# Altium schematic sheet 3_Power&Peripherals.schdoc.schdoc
size 309 x 223 mm; Symbol: Artery_A4; Device: Artery_A4; Company: Artery Technology; Version: 1.1; Page Size: A4; @Project Name: AT-START-F423 V1.1; @Page Count: 4; @Update Date: 2023-04-24; @Create Date: 2023-04-24; @Schematic Name: AT-START-F423 V1.1; @Page No: 3; @Page Name: Power&Peripherals
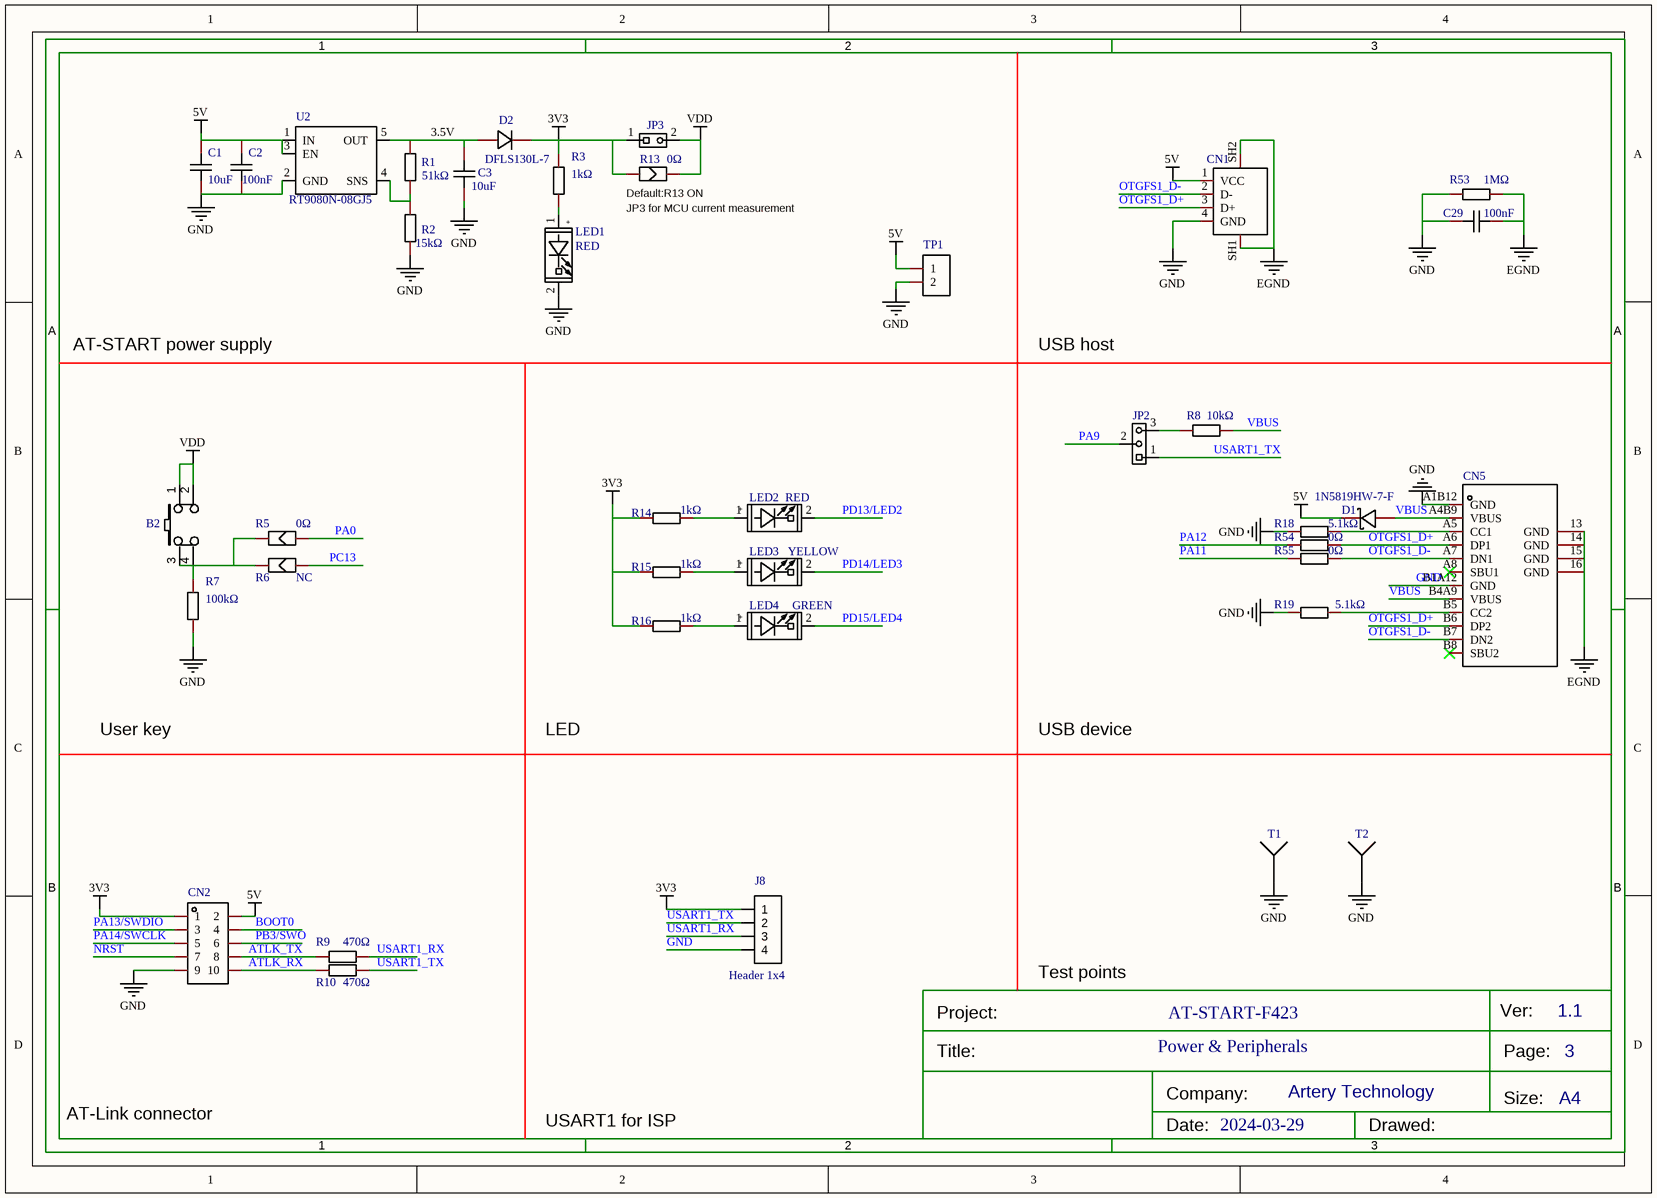
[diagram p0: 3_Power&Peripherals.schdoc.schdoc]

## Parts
B2  BUTTON_SMT,6.0x6.0x4.5mm  [BUTTON_SMT_6*6*5]  (value not drawn)
C1  value 10uF  [C0603]  (hidden comment: CL10A106KP8NNNC)
C2  value 100nF  [C0603]  (hidden comment: CC0603KRX7R9BB104)
C3  value 10uF  [C0603]  (hidden comment: CL10A106KP8NNNC)
C29  value 100nF  [C0603]  (hidden comment: CC0603KRX7R9BB104)
CN1  902-131A1011D10100  [USB-A-TH__USB-AF-90]  (value not drawn)
CN2  Z-21310110021001  [HDR-TH_10P-P2.54-V-M-R2-C5-S2.54]  (value not drawn)
CN5  TYPEC-304-BCP16  [USB-C-SMD_TYPEC-304-BCP16]  (value not drawn)
D1  1N5819HW-7-F  [SOD-123_L2.8-W1.8-LS3.7-FD]
D2  DFLS130L-7  [POWERDI-123_L2.8-W1.8-LS3.7-RD]
J8  Header 1x4  [HDR1X4]
JP2  Header 1x3  [HEADER 1X3]  (value not drawn)
JP3  NC(Header 1x2)  [HDR1X2]  (value not drawn)
LED1  RED  [LED0603]
LED2  RED  [LED0603]
LED3  YELLOW  [LED0603]
LED4  GREEN  [LED0603]
R1  value 51kΩ  [R0603]  (hidden comment: 0603WAF5102T5E)
R2  value 15kΩ  [R0603]  (hidden comment: 0603WAF1502T5E)
R3  value 1kΩ  [R0603]  (hidden comment: 0603WAF1001T5E)
R5  0Ω  [SB-PAD]
R6  NC  [SB-PAD]
R7  value 100kΩ  [R0603]  (hidden comment: 0603WAF1003T5E)
R8  value 10kΩ  [R0603]  (hidden comment: 0603WAF1002T5E)
R9  value 470Ω  [R0603]  (hidden comment: 0603WAF4700T5E)
R10  value 470Ω  [R0603]  (hidden comment: 0603WAF4700T5E)
R13  0Ω  [SB-PAD]
R14  value 1kΩ  [R0603]  (hidden comment: 0603WAF1001T5E)
R15  value 1kΩ  [R0603]  (hidden comment: 0603WAF1001T5E)
R16  value 1kΩ  [R0603]  (hidden comment: 0603WAF1001T5E)
R18  value 5.1kΩ  [R0603]  (hidden comment: 0603WAF5101T5E)
R19  value 5.1kΩ  [R0603]  (hidden comment: 0603WAF5101T5E)
R53  value 1MΩ  [R0603]  (hidden comment: RC0603FR-071ML)
R54  value 0Ω  [R0603]  (hidden comment: 0603WAF220JT5E)
R55  value 0Ω  [R0603]  (hidden comment: 0603WAF220JT5E)
T1  Testpoint  [TESTHOOK]  (value not drawn)
T2  Testpoint  [TESTHOOK]  (value not drawn)
TP1  2.54-1*2P母  [AT-START-TEST-POINT 1X2]  (value not drawn)
U2  RT9080N-08GJ5  [SOT-23-5(1)]

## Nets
3V3: CN2.1 D2.1 J8.1 JP3.1 R3.2 R13.1 R14.2 R15.2 R16.2
5V: C1.2 C2.2 CN1.1(VCC) CN2.2 D1.2(K) TP1.1 U2.1(IN) U2.3(EN)
EGND: C29.2 CN1.SH1 CN1.SH2 CN5.13(GND) CN5.14(GND) CN5.15(GND) CN5.16(GND) R53.1
GND: C1.1 C2.1 C3.1 C29.1 CN1.4(GND) CN2.9 CN5.A1B12(GND) CN5.B1A12(GND) J8.4 LED1.2(CATHODE) R2.1 R7.1 R18.2 R19.2 R53.2 T1.1 T2.1 TP1.2 U2.2(GND)
VDD: B2.1 B2.2 JP3.2 R13.2
ATLK_RX: CN2.10 R10.1
ATLK_TX: CN2.8 R9.1
BOOT0: CN2.4
NRST: CN2.7
OTGFS1_D+: CN1.3(D+) CN5.A6(DP1) CN5.B6(DP2) R54.2
OTGFS1_D-: CN1.2(D-) CN5.A7(DN1) CN5.B7(DN2) R55.2
PA0: R5.1
PA9: JP2.2
PA11: R55.1
PA12: R54.1
PA13/SWDIO: CN2.3
PA14/SWCLK: CN2.5
PB3/SWO: CN2.6
PC13: R6.1
PD13/LED2: LED2.2(CATHODE)
PD14/LED3: LED3.2(CATHODE)
PD15/LED4: LED4.2(CATHODE)
USART1_RX: J8.3 R9.2
USART1_TX: J8.2 JP2.1 R10.2
VBUS: CN5.A4B9(VBUS) CN5.B4A9(VBUS) D1.1(A) R8.2
NetB2_3: B2.3 B2.4 R5.2 R6.2 R7.2
NetC3_2: C3.2 D2.2 R1.2 U2.5(OUT)
NetCN5_A5: CN5.A5(CC1) R18.1
NetCN5_B5: CN5.B5(CC2) R19.1
NetJP2_3: JP2.3 R8.1
NetLED1_1: LED1.1(ANODE) R3.1
NetLED2_1: LED2.1(ANODE) R14.1
NetLED3_1: LED3.1(ANODE) R15.1
NetLED4_1: LED4.1(ANODE) R16.1
NetR1_1: R1.1 R2.2 U2.4(SNS)

Not connected (* = marked no-connect by the designer): CN5 A8(SBU1)* B8(SBU2)*

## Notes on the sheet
- 3.5V
- (near R13) Default:R13 ON
- (near R13) JP3 for MCU current measurement
- AT-START power supply
- USB host
- User key
- LED
- USB device
- Test points
- AT-START-F423
- Power & Peripherals
- AT-Link connector
- USART1 for ISP
- 2024-03-29

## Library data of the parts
B2 = BUTTON_SMT,6.0x6.0x4.5mm_BUTTON_SMT_6*6*5: Convert to PCB: yes
C1 C3 = CL10A106KP8NNNC: Manufacturer: SAMSUNG(三星); Add into BOM: yes; Tolerance: ±10%; Voltage Rated: 10V; Temperature Coefficient: X5R; Description: 容值:10uF;精度:±10%;额定电压:10V;温度系数:X5R;
C2 C29 = CC0603KRX7R9BB104: Manufacturer: YAGEO(国巨); Add into BOM: yes; Tolerance: ±10%; Voltage Rated: 50V; Temperature Coefficient: X7R; Description: 容值:100nF;精度:±10%;额定电压:50V;温度系数:X7R;
CN1 = 902-131A1011D10100: Manufacturer: 精拓金; Symbol: JTJ-USB-AF-08; Add into BOM: yes; Connector Type: Type-A; Gender: 母座; Number of Contacts: 4; Number of Ports: 1; Description: 连接器类型:Type-A;标准:USB 2.0;公母:母座;触点数量:4;端口数量:1;
CN2 = Z-21310110021001: Manufacturer: Nextron(台湾正凌); Add into BOM: yes; Pitch: 2.54mm; Description: 间距:2.54mm;总PIN位数:10;排数:2;插针结构:-;行距:2.54mm;安装类型:直插;圆针/方针:-;额定电流:-;额定电压:-;配合针长度:-;塑高:-;触头材质:黄铜;触头镀层:-;颜色:黑色;
CN5 = TYPEC-304-BCP16: 连接器类型:Type-C;标准:USB 3.1;公母:母座;触点数量:16.0;端口数量:1;安装方式:卧贴;额定电流 - 电源:3A;工作温度范围:-25~+85;焊接温度(最大值):260;; Manufacturer: XUNPU(讯普); Add into BOM: yes; Connector Type: Type-C; Gender: 母座; Number of Contacts: 16.0; Number of Ports: 1; Mounting Sytle: 卧贴; Current Rating - Power (Max): 3A; Welding Temperature (Max): 260
D1 = 1N5819HW-7-F: 直流反向耐压(Vr):40V;平均整流电流(Io):1A;正向压降(Vf):450mV@1A;; Manufacturer: DIODES(美台); Add into BOM: yes; Reverse Voltage (Vr): 40V; Average Rectified Current (Io): 1A
D2 = DFLS130L-7_POWERDI-123_L2.8-W1.8-LS3.7-RD: Manufacturer: Diodes Incorporated; Paste Type: expand; Convert to PCB: yes
J8 = Header 1x4: Convert to PCB: yes
JP2 = Header 1x3: Convert to PCB: yes
JP3 = NC(Header 1x2): Convert to PCB: yes
LED1 = RED_LED0603(1): Symbol: RED(1); Convert to PCB: yes
LED2 = RED_LED0603: Convert to PCB: yes
LED3 = YELLOW_LED0603: Convert to PCB: yes
LED4 = GREEN_LED0603: Convert to PCB: yes
R1 = 0603WAF5102T5E: 电阻类型:厚膜电阻;阻值:51kΩ;精度:±1%;功率:1/10W;温度系数:±100ppm/;最大工作电压:75V;工作温度范围:-55~+155;; Manufacturer: UNI-ROYAL(厚声); Add into BOM: yes; Tolerance: ±1%; Power(Watts): 1/10W; Overload Voltage (Max): 75V
R2 = 0603WAF1502T5E: 电阻类型:厚膜电阻;阻值:15kΩ;精度:±1%;功率:1/10W;温度系数:±100ppm/;最大工作电压:75V;工作温度范围:-55~+155;; Manufacturer: UNI-ROYAL(厚声); Add into BOM: yes; Tolerance: ±1%; Power(Watts): 1/10W; Overload Voltage (Max): 75V
R3 R14-R16 = 0603WAF1001T5E: 电阻类型:厚膜电阻;阻值:1kΩ;精度:±1%;功率:1/10W;温度系数:±100ppm/;最大工作电压:75V;工作温度范围:-55~+155;; Manufacturer: UNI-ROYAL(厚声); Add into BOM: yes; Tolerance: ±1%; Power(Watts): 1/10W; Overload Voltage (Max): 75V
R5 R13 = NC_SB-PAD: Symbol: NC; Convert to PCB: yes
R6 = NC_SB-PAD: Convert to PCB: yes
R7 = 0603WAF1003T5E: 电阻类型:厚膜电阻;阻值:100kΩ;精度:±1%;功率:1/10W;温度系数:±100ppm/;最大工作电压:75V;工作温度范围:-55~+155;; Manufacturer: UNI-ROYAL(厚声); Add into BOM: yes; Tolerance: ±1%; Power(Watts): 1/10W; Overload Voltage (Max): 75V
R8 = 0603WAF1002T5E: 电阻类型:厚膜电阻;阻值:10kΩ;精度:±1%;功率:1/10W;温度系数:±100ppm/;最大工作电压:75V;工作温度范围:-55~+155;; Manufacturer: UNI-ROYAL(厚声); Add into BOM: yes; Tolerance: ±1%; Power(Watts): 1/10W; Overload Voltage (Max): 75V
R9 R10 = 0603WAF4700T5E: 电阻类型:厚膜电阻;阻值:470Ω;精度:±1%;功率:1/10W;温度系数:±100ppm/;最大工作电压:75V;工作温度范围:-55~+155;; Manufacturer: UNI-ROYAL(厚声); Add into BOM: yes; Tolerance: ±1%; Power(Watts): 1/10W; Overload Voltage (Max): 75V
R18 R19 = 0603WAF5101T5E: 电阻类型:厚膜电阻;阻值:5.1kΩ;精度:±1%;功率:1/10W;温度系数:±100ppm/;最大工作电压:75V;工作温度范围:-55~+155;; Manufacturer: UNI-ROYAL(厚声); Add into BOM: yes; Tolerance: ±1%; Power(Watts): 1/10W; Overload Voltage (Max): 75V
R53 = RC0603FR-071ML: 阻值:1MΩ;精度:±1%;功率:100mW;温度系数:±100ppm/;最大工作电压:75V;工作温度范围:-55~+155;; Manufacturer: YAGEO(国巨); Add into BOM: yes; Tolerance: ±1%; Power(Watts): 100mW; Overload Voltage (Max): 75V
R54 R55 = 0603WAF220JT5E: 电阻类型:厚膜电阻;阻值:22Ω;精度:±1%;功率:100mW;温度系数:±100ppm/;最大工作电压:75V;工作温度范围:-55~+155;; Manufacturer: UNI-ROYAL(厚声); Add into BOM: yes; Tolerance: ±1%; Power(Watts): 100mW; Overload Voltage (Max): 75V
T1 = Testpoint_TESTHOOK: Convert to PCB: yes
T2 = Testpoint: Convert to PCB: yes
TP1 = 2.54-1*2P母: Manufacturer: BOOMELE(博穆精密); Symbol: Header-Female-2.54_1x2; Add into BOM: yes; Pitch: 2.54mm; Number of Holes: 2; Holes Structure: 1x2P; Description: 间距:2.54mm;总孔位数:2;排数:1;插孔结构:1x2P;行距:-;安装类型:直插;塑高:-;触头材质:-;触头镀层:-;
U2 = RT9080N-08GJ5_SOT-23-5: Convert to PCB: yes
